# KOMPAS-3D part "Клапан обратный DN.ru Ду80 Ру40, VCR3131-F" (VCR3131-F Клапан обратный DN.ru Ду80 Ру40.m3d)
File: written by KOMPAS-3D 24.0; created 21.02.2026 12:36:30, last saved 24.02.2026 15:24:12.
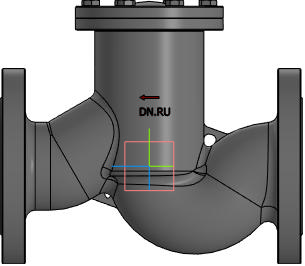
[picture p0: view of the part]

Document properties: Автор: R2D2; Полное имя файла: VCR3131-F Клапан обратный DN.ru Ду80 Ру40.cdw

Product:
- Part/product: Клапан обратный DN.ru Ду80 Ру40  | designation VCR3131-F
    Масса: 20.5
    Раздел спецификации: Прочие изделия
    Форматы листов документа: A2
    Примечание: D100-04043
    additional columns: D100-04043

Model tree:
1. Операция без истории:1

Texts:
  VCR3131-F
